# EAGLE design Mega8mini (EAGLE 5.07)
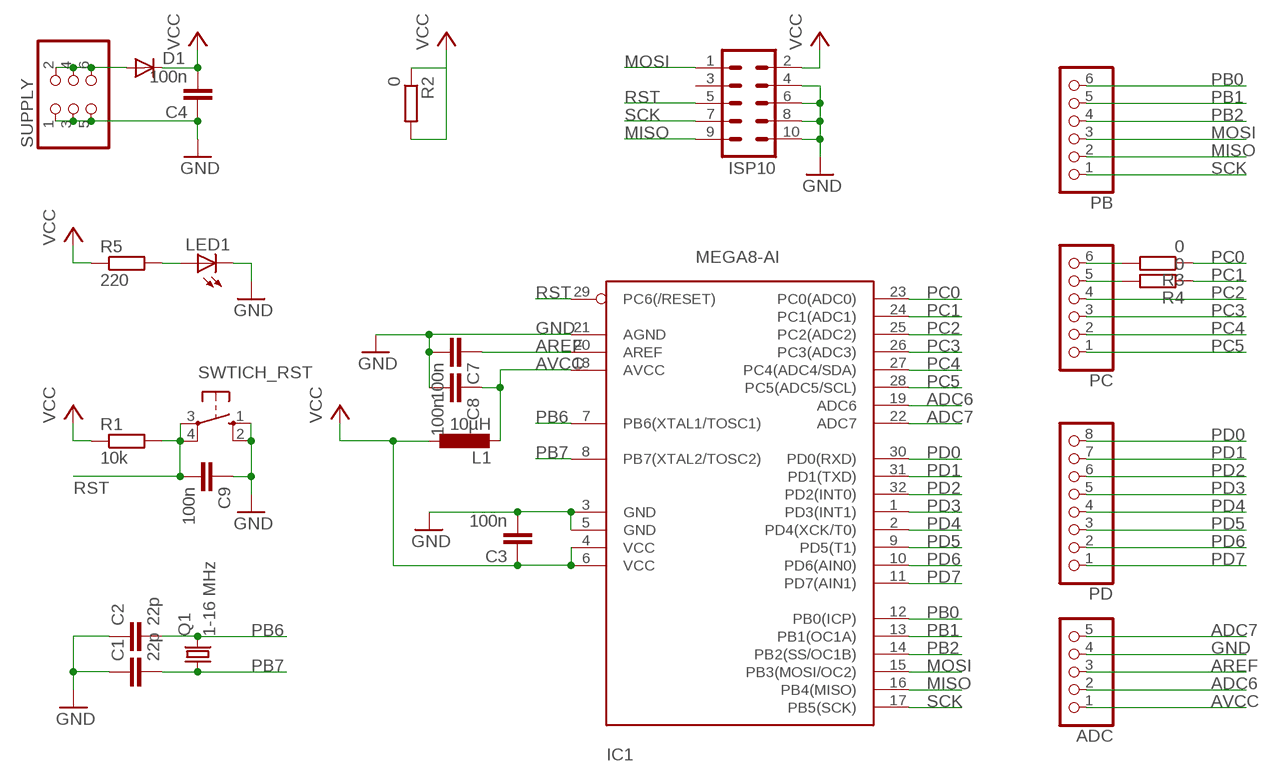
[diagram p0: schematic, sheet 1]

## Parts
ADC  PINHD-1X5  [1X05]
C1  22p  C-EUC0805  [C0805]
C2  22p  C-EUC0805  [C0805]
C3  100n  C-EUC0805  [C0805]
C4  100n  C-EUC0805  [C0805]
C7  100n  C-EUC0805  [C0805]
C8  100n  C-EUC0805  [C0805]
C9  100n  C-EUC0805  [C0805]
D1  DIODE-MINIMELF  [MINIMELF]
IC1  MEGA8-AI  [TQFP32-08]
ISP10  ML10  [ML10]
L1  10µH  L-EUL2012C  [L2012C]
LED1  LED3MM  [LED3MM]
PB  PINHD-1X6  [1X06]
PC  PINHD-1X6  [1X06]
PD  PINHD-1X8  [1X08]
Q1  1-16 MHz  CRYSTALHC49S  [HC49/S]
R1  10k  R-EU_R0805  [R0805]
R2  0  R-EU_R1206  [R1206]
R3  0  R-EU_R1206  [R1206]
R4  0  R-EU_R1206  [R1206]
R5  220  R-EU_R0805  [R0805]
SUPPLY  PINHD-2X3  [2X03]
SWTICH_RST  10-XX  [B3F-10XX]

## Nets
ADC6: ADC.2 IC1.19(ADC6)
ADC7: ADC.5 IC1.22(ADC7)
AREF: ADC.3 C7.1 IC1.20(AREF)
AVCC: ADC.1 C8.1 IC1.18(AVCC) L1.2
GND: ADC.4 C1.1 C2.1 C3.2 C4.1 C7.2 C8.2 C9.1 IC1.3(GND) IC1.5(GND) IC1.21(AGND) ISP10.4 ISP10.6 ISP10.8 ISP10.10 LED1.K(C) SUPPLY.1 SUPPLY.3 SUPPLY.5 SWTICH_RST.1(S) SWTICH_RST.2(S1)
MISO: IC1.16(PB4(MISO)) ISP10.9 PB.2
MOSI: IC1.15(PB3(MOSI/OC2)) ISP10.1 PB.3
N$1: D1.A SUPPLY.2 SUPPLY.4 SUPPLY.6
N$3: PC.5 R4.2
N$4: PC.6 R3.2
N$6: LED1.A R5.2
PB0: IC1.12(PB0(ICP)) PB.6
PB1: IC1.13(PB1(OC1A)) PB.5
PB2: IC1.14(PB2(SS/OC1B)) PB.4
PB6: C2.2 IC1.7(PB6(XTAL1/TOSC1)) Q1.2
PB7: C1.2 IC1.8(PB7(XTAL2/TOSC2)) Q1.1
PC0: IC1.23(PC0(ADC0)) R3.1
PC1: IC1.24(PC1(ADC1)) R4.1
PC2: IC1.25(PC2(ADC2)) PC.4
PC3: IC1.26(PC3(ADC3)) PC.3
PC4: IC1.27(PC4(ADC4/SDA)) PC.2
PC5: IC1.28(PC5(ADC5/SCL)) PC.1
PD0: IC1.30(PD0(RXD)) PD.8
PD1: IC1.31(PD1(TXD)) PD.7
PD2: IC1.32(PD2(INT0)) PD.6
PD3: IC1.1(PD3(INT1)) PD.5
PD4: IC1.2(PD4(XCK/T0)) PD.4
PD5: IC1.9(PD5(T1)) PD.3
PD6: IC1.10(PD6(AIN0)) PD.2
PD7: IC1.11(PD7(AIN1)) PD.1
RST: C9.2 IC1.29(PC6(/RESET)) ISP10.5 R1.2 SWTICH_RST.3(P) SWTICH_RST.4(P1)
SCK: IC1.17(PB5(SCK)) ISP10.7 PB.1
VCC: C3.1 C4.2 D1.C IC1.4(VCC) IC1.6(VCC) ISP10.2 L1.1 R1.1 R2.1 R2.2 R5.1
Unconnected: ISP10.3

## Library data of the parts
ADC = pinhead:PINHD-1X5: PIN HEADER
C1-C4 C7-C9 = rcl:C-EU: CAPACITOR, European symbol
D1 = diode:DIODE-: DIODE
IC1 = atmel:MEGA8: MICROCONTROLLER 8 Kbytes FLASH 1 kbytes SRAM 512 bytes EEPROM USART 6-channel 10 bit ADC 2-channel 8 bit ADC Source: avr.lbr
ISP10 = con-harting-ml:ML10: HARTING
L1 = rcl:L-EU: INDUCTOR, European symbol
LED1 = led:LED: LED
PB PC = pinhead:PINHD-1X6: PIN HEADER
PD = pinhead:PINHD-1X8: PIN HEADER
Q1 = crystal:CRYSTAL: CRYSTAL
R1-R5 = rcl:R-EU_: RESISTOR, European symbol
SUPPLY = pinhead:PINHD-2X3: PIN HEADER
SWTICH_RST = switch-omron:10-XX: OMRON SWITCH

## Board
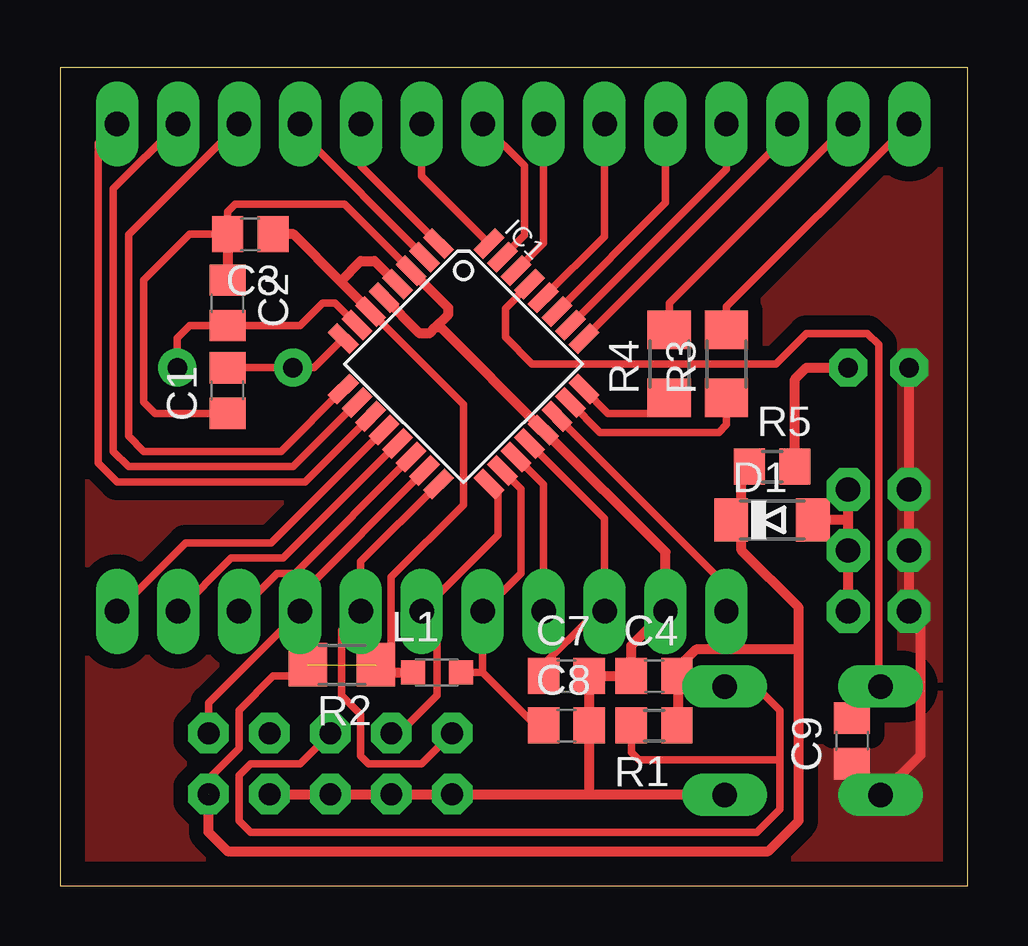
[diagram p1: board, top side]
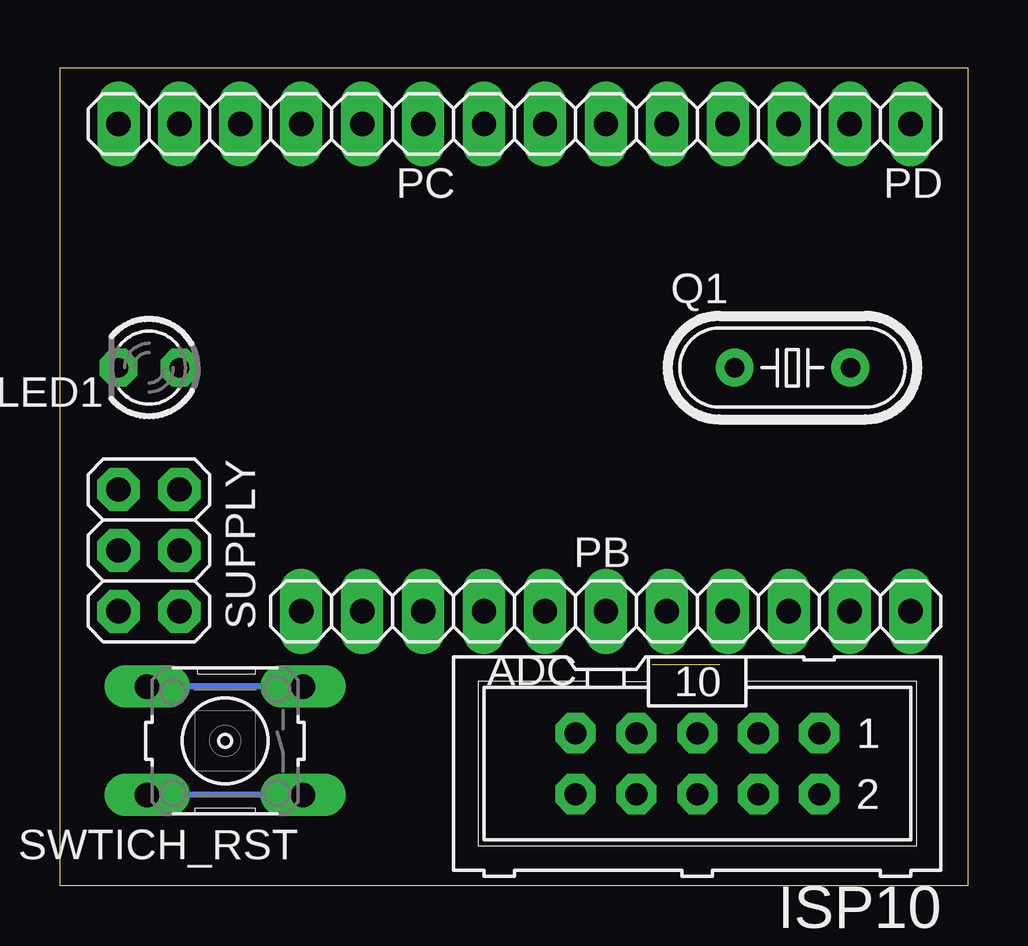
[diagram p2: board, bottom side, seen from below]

Size 37.84 x 34.1 mm. Coordinates in mm from the lower left corner, seen from the top.
Outline: 0,0 37.84,0 37.84,34.1 0,34.1 0,0
Copper layers (1*16): Top 0.035mm / dielectric 1.5mm / Bottom 0.035mm
Design rules "default *": minimum track width 10mil, minimum drill 24mil, track to track 8mil, track to pad 8mil, pad to pad 8mil, via to via 8mil, smd to smd 8mil, copper to edge 40mil, drill to drill 8mil, minimum pad ring 15mil, minimum via ring 8mil, stop-mask expansion 4mil, vias tented up to drill 0mil, thermal gap 10mil

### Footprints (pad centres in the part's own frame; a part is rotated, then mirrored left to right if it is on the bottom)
1X05 = drill 1.016 long: 1 -5.08,0; 2 -2.54,0; 3 0,0; 4 2.54,0; 5 5.08,0
C0805 = smd 1.3 x 1.5: 1 -0.95,0; 2 0.95,0
MINIMELF = smd 1.4 x 1.8: A 1.7,0; C -1.7,0
TQFP32-08 = smd 1.27 x 0.559: 1 -4.293,2.8; 2 -4.293,2; 3 -4.293,1.2; 4 -4.293,0.4; 5 -4.293,-0.4; 6 -4.293,-1.2; 7 -4.293,-2; 8 -4.293,-2.8; 17 4.293,-2.8; 18 4.293,-2; 19 4.293,-1.2; 20 4.293,-0.4; 21 4.293,0.4; 22 4.293,1.2; 23 4.293,2; 24 4.293,2.8 | smd 0.559 x 1.27: 9 -2.8,-4.293; 10 -2,-4.293; 11 -1.2,-4.293; 12 -0.4,-4.293; 13 0.4,-4.293; 14 1.2,-4.293; 15 2,-4.293; 16 2.8,-4.293; 25 2.8,4.293; 26 2,4.293; 27 1.2,4.293; 28 0.4,4.293; 29 -0.4,4.293; 30 -1.2,4.293; 31 -2,4.293; 32 -2.8,4.293
ML10 = drill 0.914 octagon: 1 -5.08,-1.27; 2 -5.08,1.27; 3 -2.54,-1.27; 4 -2.54,1.27; 5 0,-1.27; 6 0,1.27; 7 2.54,-1.27; 8 2.54,1.27; 9 5.08,-1.27; 10 5.08,1.27
L2012C = smd 1 x 1: 1 -1,0; 2 1,0
LED3MM = drill 0.813 octagon: A -1.27,0; K 1.27,0
1X06 = drill 1.016 long: 1 -6.35,0; 2 -3.81,0; 3 -1.27,0; 4 1.27,0; 5 3.81,0; 6 6.35,0
1X08 = drill 1.016 long: 1 -8.89,0; 2 -6.35,0; 3 -3.81,0; 4 -1.27,0; 5 1.27,0; 6 3.81,0; 7 6.35,0; 8 8.89,0
HC49/S = drill 0.813 round: 1 -2.413,0; 2 2.413,0
R0805 = smd 1.3 x 1.5: 1 -0.95,0; 2 0.95,0
R1206 = smd 1.6 x 1.803: 1 -1.422,0; 2 1.422,0
2X03 = drill 1.016 octagon: 1 -2.54,-1.27; 2 -2.54,1.27; 3 0,-1.27; 4 0,1.27; 5 2.54,-1.27; 6 2.54,1.27
B3F-10XX = drill 1.016 long: 1 -3.251,2.261; 2 3.251,2.261; 3 -3.251,-2.261; 4 3.251,-2.261

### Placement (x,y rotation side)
ADC  22.7,11.43 180 bottom
C1  6.99,20.64 90 top
C2  6.99,24.29 270 top
C3  7.94,27.15 180 top
C4  24.77,8.73 0 top
C7  21.11,8.73 0 top
C8  21.11,6.67 0 top
C9  33.02,6.03 90 top
D1  29.69,15.24 0 top
IC1  16.83,21.75 315 top
ISP10  11.27,5.08 180 bottom
L1  15.72,8.89 0 top
LED1  34.13,21.59 180 bottom
PB  8.73,11.43 0 bottom
PC  29.05,31.75 180 bottom
PD  11.27,31.75 180 bottom
Q1  7.3,21.59 0 bottom
R1  24.76,6.67 180 top
R2  11.75,9.21 180 top
R3  27.78,21.75 90 top
R4  25.4,21.75 90 top
R5  29.69,17.46 0 top
SUPPLY  34.13,13.97 270 bottom
SWTICH_RST  30.96,6.03 180 bottom

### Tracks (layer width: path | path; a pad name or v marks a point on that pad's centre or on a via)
ADC6
  Top 0.305: IC1.19 20.16,16.72 ADC.2
ADC7
  Top 0.305: IC1.22 27.78,12.49 ADC.5
AREF
  Top 0.305: C7.1 20.16,9.21 22.07,11.11 22.38,11.11 ADC.3 22.7,15.31 IC1.20
AVCC
  Top 0.305: IC1.18 19.21,16.54 19.21,13.02 ADC.1 | ADC.1 | L1.2 17.62,8.89 | 17.62,8.89 19.68,6.83 20,6.83 C8.1 | 17.62,8.89 ADC.1 | 17.62,8.89
GND
  Top 0.305: C2.1 | C1.1 3.97,19.68 3.49,20.16 3.49,25.24 5.4,27.15 C3.2 6.99,28.1 7.3,28.42 11.86,28.42 IC1.3 | 21.59,8.57 21.75,8.73 C7.2 22.54,9.21
  Top 0.406: IC1.5 14.99,23.02 15.4,23.02 15.64,23.26 | 15.64,23.26 16.19,23.81 16.19,24.08 IC1.3 | 15.64,23.26 15.88,23.26 IC1.21 25.24,13.9 ADC.4 23.82,10 C4.1 C7.2 | SWTICH_RST.1 27.67,3.81 22.06,3.81 | ISP10.4 ISP10.6 ISP10.8 ISP10.10 22.06,3.81 | C7.2 C8.2 22.06,3.81 | C7.2 | LED1.K SUPPLY.1 SUPPLY.3 SUPPLY.5 35.88,10.95 35.88,5.44 SWTICH_RST.2 33.02,4.96 C9.1 | LED1.K | C3.2 C2.1
  Bottom 0.254: SWTICH_RST.1 SWTICH_RST.2
  pour Top (isolate 0.61, no thermals): 38.89,30.48 29.21,30.48 29.37,-0.95 38.89,-0.95
MISO
  Top 0.305: ISP10.9 15.08,5.08 12.86,5.08 12.54,5.4 12.54,7.14 11.75,7.94 11.75,10.64 PB.2 12.54,13.5 IC1.16
MOSI
  Top 0.305: ISP10.1 6.19,7.62 PB.3 10,12.09 IC1.15
N$1
  Top 0.406: 32.86,15.4 SUPPLY.4 SUPPLY.6 | 32.86,15.4 SUPPLY.2 | D1.A 32.7,15.24 32.86,15.4
N$3
  Top 0.305: PC.5 25.4,24.29 R4.2
N$4
  Top 0.305: PC.6 27.78,24.13 R3.2
N$5
  pour Top (isolate 0.61): -0.64,17.62 9.68,17.62 9.52,-0.48 -0.64,-0.48
N$6
  Top 0.406: LED1.A 31.11,21.59 30.64,21.11 R5.2
PB0
  Top 0.305: PB.6 5.24,14.29 8.8,14.29 IC1.12 | PB.6
PB1
  Top 0.305: PB.5 7.14,13.65 9.3,13.65 IC1.13 | PB.5
PB2
  Top 0.305: PB.4 | PB.4 9.05,13.02 9.79,13.02 IC1.14
PB6
  Top 0.305: Q1.2 4.89,22.83 5.4,23.34 C2.2 | C2.2 | IC1.7 11.46,24.29 10.95,24.29 10,23.34 C2.2
PB7
  Top 0.305: C1.2 Q1.1 10.6,21.59 IC1.8
PC0
  Top 0.305: IC1.23 22.51,18.89 27.46,18.89 27.78,19.21 R3.1 | R3.1
PC1
  Top 0.305: IC1.24 22.85,19.68 25.08,19.68 25.4,20 R4.1
PC2
  Top 0.305: IC1.25 30.32,31.28 PC.4
PC3
  Top 0.305: IC1.26 27.78,29.87 PC.3
PC4
  Top 0.305: IC1.27 25.24,28.46 PC.2
PC5
  Top 0.305: IC1.28 22.7,27.06 PC.1
PD0
  Top 0.305: PD.8 20.16,26.78 IC1.30
PD1
  Top 0.305: IC1.31 19.37,27.12 19.37,30 PD.7
PD2
  Top 0.305: IC1.32 15.08,29.57 PD.6
PD3
  Top 0.305: IC1.1 12.54,29.99 PD.5
PD4
  Top 0.305: IC1.2 10,31.4 PD.4
PD5
  Top 0.305: PD.3 2.86,27.15 2.86,18.73 3.49,18.1 9.22,18.1 IC1.9
PD6
  Top 0.305: PD.2 2.22,29.05 2.22,18.1 2.86,17.46 9.71,17.46 IC1.10
PD7
  Top 0.305: PD.1 1.59,30.96 1.59,17.62 2.38,16.83 10.21,16.83 IC1.11
RST
  Top 0.305: ISP10.5 | ISP10.5 10,5.08 7.94,5.08 7.46,4.6 7.46,2.7 7.94,2.22 29.05,2.22 30,3.17 30,5.24 | IC1.29 18.57,24.06 18.57,22.86 19.68,21.75 23.02,21.75 23.34,21.75 29.84,21.75 31.11,23.02 33.66,23.02 34.13,22.54 34.13,8.37 SWTICH_RST.4 | R1.2 23.82,5.55 24.13,5.24 30,5.24 | SWTICH_RST.3 29.01,8.29 30,7.3 30,5.24
  Top 0.406: C9.2 33.02,7.11 SWTICH_RST.4
  Bottom 0.254: SWTICH_RST.3 SWTICH_RST.4
SCK
  Top 0.305: ISP10.7 14.13,6.35 15.72,7.94 15.72,11.11 15.4,11.43 PB.1 18.26,14.6 18.26,16.35 IC1.17
VCC  (2 unrouted)
  Top 0.305: IC1.6 16.83,20.05 16.83,15.88 13.81,12.86 13.81,9.85 R2.1 | ISP10.2 6.19,4.45 7.46,5.71 7.46,7.3 8.89,8.73 9.85,8.73 R2.2 | 25.76,8.73 C4.2 | 25.76,8.73
  Top 0.406: R1.1 25.76,6.72 25.76,8.73 25.76,9.1 26.51,9.84 30.8,9.84 | R5.1 28.74,17.31 28.42,16.99 28.42,15.67 D1.C 28.42,14.81 28.42,13.97 30.8,11.59 30.8,9.84 | 30.8,9.84 30.8,2.7 29.53,1.43 6.99,1.43 6.19,2.22 ISP10.2 | ISP10.2 | IC1.6 11.69,25.19 | IC1.4 13.11,26.04 12.54,26.04 11.69,25.19 | 11.69,25.19 | L1.1 13.49,8.89 R2.1 | 11.69,25.19 9.73,27.15 C3.1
